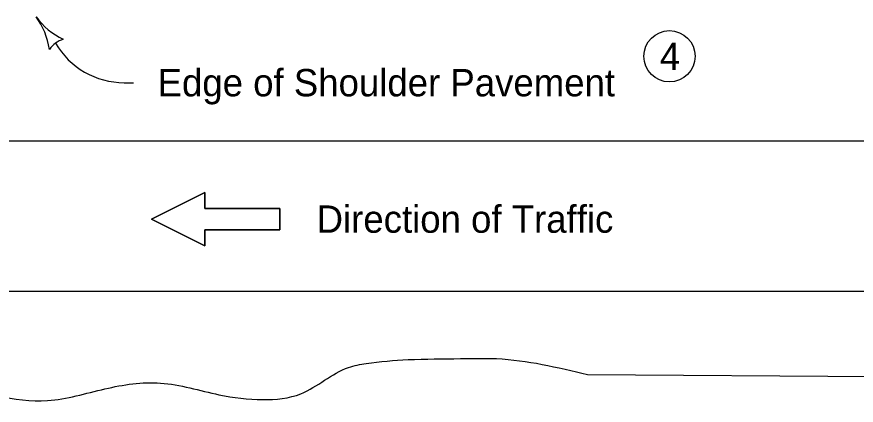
# Model space of a CAD drawing. Extents: x 10133 to 81668, y 7924 to 12229.
# Drawn here: x 11037.4 to 11528.5, y 9467.4 to 9694.7 of the extents above; entities that cross this region are included whole.
import ezdxf

# ---------------------------------------------------------------- set-up
doc = ezdxf.new("R2010")
doc.units = 0
for name, color, linetype in [('dsnTextFinalPlan', 7, 'Continuous'), ('Level 11', 7, 'Continuous'), ('Level 12', 7, 'Continuous'), ('Level 20', 7, 'Continuous'), ('Level 4', 7, 'Continuous'), ('Level 6', 7, 'Continuous')]:
    doc.layers.add(name, color=color, linetype=linetype)

msp = doc.modelspace()

# ---------------------------------------------------------------- linework, layer by layer
at = {"layer": 'dsnTextFinalPlan'}
for p, q in [((10368.86, 9622), (11982.65, 9622)), ((11371.34, 9485.38), (11700.54, 9482.92))]:
    msp.add_line(p, q, dxfattribs=at)
msp.add_spline([(10372.93, 9478.29), (10382.36, 9480.86), (10412.58, 9480.29), (10440.52, 9472.31), (10467.89, 9471.16), (10486.14, 9476.87), (10512.94, 9476.3), (10537.46, 9471.74), (10561.41, 9475.16), (10578.52, 9480.29), (10618.43, 9472.88), (10645.23, 9468.88), (10669.75, 9478.01), (10692.56, 9479.72), (10731.34, 9474.02), (10730.77, 9474.02), (10751.92, 9472.41), (10788.99, 9475.27), (10814.08, 9478.12), (10832.9, 9481.54), (10856.85, 9480.97), (10878.51, 9477.55), (10904.17, 9472.98), (10937.82, 9474.13), (10969.18, 9480.4), (10994.27, 9480.4), (11026.2, 9472.98), (11055.29, 9470.13), (11088.93, 9476.98), (11121.43, 9480.4), (11155.65, 9473.55), (11181.31, 9470.7), (11203.54, 9474.13), (11231.49, 9489.53), (11241.75, 9491.81), (11266.27, 9494.09), (11296.93, 9494.66), (11318.03, 9494.66), (11371.34, 9485.38)], degree=3, dxfattribs=at)
at = {"layer": 'Level 11'}
msp.add_lwpolyline([(11191.15, 9582.56), (11191.15, 9570.06), (11147.4, 9570.06), (11147.4, 9560.68), (11116.15, 9576.31), (11147.4, 9591.93), (11147.4, 9582.56)], close=True, dxfattribs=at)
at = {"layer": 'Level 12'}
msp.add_circle((11419.2, 9671.55), 15, dxfattribs=at)
at = {"layer": 'Level 20'}
msp.add_lwpolyline([(11147.4, 9582.56), (11147.4, 9591.93), (11116.15, 9576.31), (11147.4, 9560.68), (11147.4, 9570.06), (11191.15, 9570.06), (11191.15, 9582.56), (11147.4, 9582.56)], dxfattribs=at)
at = {"layer": 'Level 4'}
msp.add_line((10352.26, 9534.09), (11994.29, 9534.09), dxfattribs=at)
at = {"layer": 'Level 6'}
msp.add_line((11100.1, 9656.12), (11105.55, 9656.12), dxfattribs=at)
for centre, radius, start, end in [((11082.84, 9719.87), 42.5, 216.3726, 244.445), ((11014.4, 9669.46), 42.5, 8.3001, 36.3726), ((11069.75, 9665.97), 16.42, 108.6392, 144.1059), ((11100.16, 9702.58), 46.46, 210.2274, 270)]:
    msp.add_arc(centre, radius, start, end, dxfattribs=at)

# ---------------------------------------------------------------- texts
at = {"layer": 'Level 12'}
msp.add_text('4', height=16, dxfattribs=at).set_placement((11413.53, 9663.55))
at = {"layer": 'Level 6'}
for s, p in [('Edge of Shoulder Pavement', (11119.74, 9648.12)), ('Direction of Traffic', (11212.76, 9568.31))]:
    msp.add_text(s, height=16, dxfattribs=at).set_placement(p)

doc.saveas('drawing.dxf')
